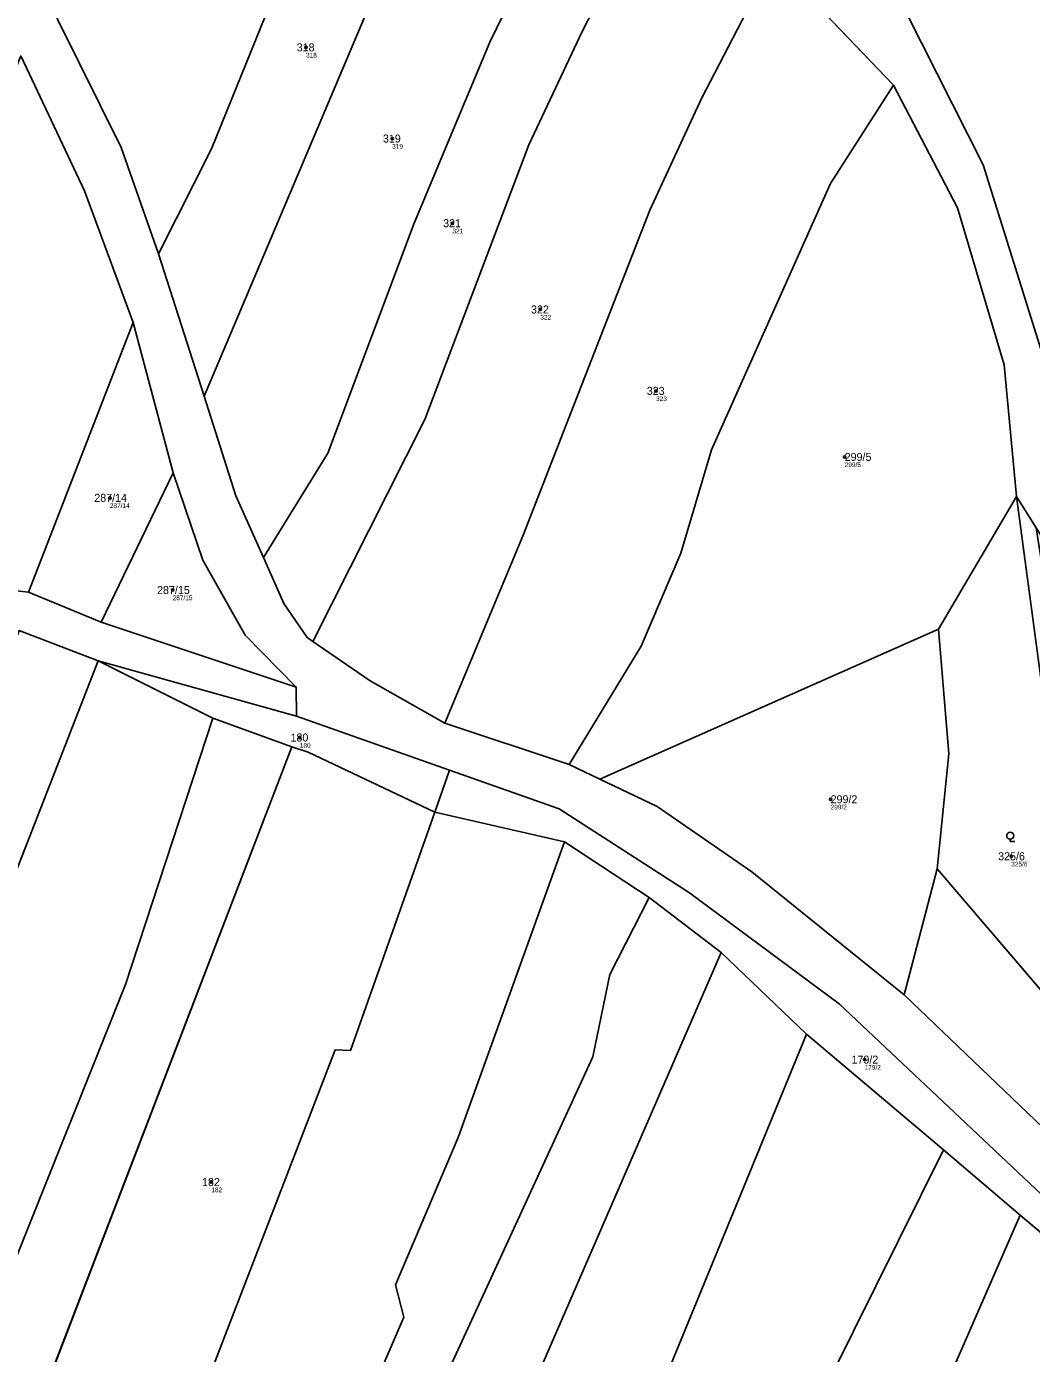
# Model space of a CAD drawing. Extents: x -767985 to -763816, y -1059600 to -1057360.
# Drawn here: x -766182.2 to -765968.6, y -1058497.3 to -1058215.3 of the extents above; entities that cross this region are included whole.
import ezdxf

# ---------------------------------------------------------------- set-up
doc = ezdxf.new("R2010")
doc.units = 0
for name, color, linetype in [('Definiční body', 7, 'Continuous'), ('Hranice parcel', 7, 'Continuous'), ('Parcelní čísla', 7, 'Continuous'), ('Polygon parcely', 7, 'Continuous'), ('Značky kultur', 7, 'Continuous')]:
    doc.layers.add(name, color=color, linetype=linetype)

msp = doc.modelspace()

# ---------------------------------------------------------------- linework, layer by layer
at = {"layer": 'Definiční body'}
for centre in [(-766122.78, -1058219.76994), (-766104.46, -1058239.13994), (-766091.66, -1058257.12994), (-766072.99, -1058275.45994), (-766048.38, -1058292.74994), (-766008.3, -1058306.77994), (-766164.47, -1058315.47994), (-766151.13, -1058335.06994), (-766124.1, -1058366.39994), (-766011.29, -1058379.51994), (-765972.91, -1058391.62994), (-766004.07, -1058434.83994), (-766142.9, -1058460.84994)]:
    msp.add_circle(centre, 0.25, dxfattribs=at)
at = {"layer": 'Hranice parcel'}
for p, q in [((-766144.44, -1058293.9), (-766085.7, -1058155.04)), ((-766023.45, -1058201.07), (-765997.93, -1058227.82)), ((-766144.44, -1058293.9), (-766154.16, -1058263.63)), ((-766181.77, -1058335.55), (-766159.52, -1058278.21)), ((-766159.52, -1058278.21), (-766150.99, -1058310.19)), ((-766166.32, -1058341.89), (-766150.99, -1058310.19)), ((-765988.34, -1058343.38), (-765971.77, -1058315.2)), ((-765967.58, -1058321.82), (-765971.77, -1058315.2)), ((-766181.77, -1058335.55), (-766166.32, -1058341.89)), ((-766166.32, -1058341.89), (-766124.85, -1058355.68)), ((-765988.34, -1058343.38), (-766060.34, -1058375.22)), ((-766166.97, -1058350.08), (-766183.72, -1058343.65)), ((-766166.97, -1058350.08), (-766234.65, -1058523.62)), ((-766124.77, -1058361.86), (-766166.97, -1058350.08)), ((-766166.97, -1058350.08), (-766142.57, -1058362.31)), ((-766124.85, -1058355.68), (-766124.77, -1058361.86)), ((-766125.82, -1058368.4), (-766142.57, -1058362.31)), ((-766124.77, -1058361.86), (-766092.25, -1058373.31)), ((-766066.84, -1058372.11), (-766093.28, -1058363.36)), ((-766193.09, -1058543.53), (-766125.82, -1058368.4)), ((-766092.25, -1058373.31), (-766095.42, -1058382.27)), ((-766060.34, -1058375.22), (-766066.84, -1058372.11)), ((-766067.85, -1058388.57), (-766095.42, -1058382.27)), ((-766049.88, -1058400.36), (-766067.85, -1058388.57)), ((-765995.67, -1058421.04), (-765988.63, -1058394.32)), ((-765936.48, -1058455.29), (-765988.63, -1058394.32)), ((-766034.52, -1058412.06), (-766049.88, -1058400.36)), ((-766016.38, -1058429.41), (-766034.52, -1058412.06)), ((-765987.29, -1058454.03), (-766016.38, -1058429.41)), ((-765970.97, -1058467.85), (-765987.29, -1058454.03)), ((-765949.24, -1058486.24), (-765970.97, -1058467.85))]:
    msp.add_line(p, q, dxfattribs=at)
for points in [[(-766154.16, -1058263.63), (-766142.88, -1058241.36), (-766102.9, -1058142.76)], [(-766131.83, -1058328.16), (-766118.17, -1058305.96), (-766099.79, -1058257.11), (-766083.71, -1058218.7), (-766061.29, -1058172.55)], [(-766121.31, -1058346.01), (-766097.55, -1058298.8), (-766075.41, -1058240.45), (-766064.09, -1058216.4), (-766047.12, -1058183.23)], [(-766093.28, -1058363.36), (-766076.64, -1058323.43), (-766049.74, -1058254.37), (-766038.76, -1058230.6), (-766023.45, -1058201.07)], [(-766154.16, -1058263.63), (-766162.06, -1058241.04), (-766179.98, -1058204.86)], [(-765961.17, -1058301.29), (-765978.87, -1058244.75), (-765995.2, -1058212.34)], [(-766183.4, -1058221.59), (-766169.87, -1058250.23), (-766159.52, -1058278.21)], [(-765997.93, -1058227.82), (-766011.33, -1058248.72), (-766036.6, -1058305.3), (-766043.12, -1058327.25), (-766051.55, -1058347.01), (-766066.84, -1058372.11)], [(-765997.93, -1058227.82), (-765984.33, -1058253.84), (-765974.41, -1058287.25), (-765971.77, -1058315.2)], [(-766131.83, -1058328.16), (-766137.71, -1058315.03), (-766144.44, -1058293.9)], [(-766150.99, -1058310.19), (-766144.69, -1058328.75), (-766135.72, -1058344.67), (-766124.85, -1058355.68)], [(-765971.77, -1058315.2), (-765965.74, -1058360.18), (-765957.89, -1058393.07), (-765936.48, -1058455.29)], [(-766121.31, -1058346.01), (-766122.51, -1058345.18), (-766127.47, -1058337.9), (-766131.83, -1058328.16)], [(-766228.56, -1058334.02), (-766207.88, -1058332.62), (-766181.77, -1058335.55)], [(-765988.63, -1058394.32), (-765986.13, -1058369.89), (-765988.34, -1058343.38)], [(-766093.28, -1058363.36), (-766109.12, -1058354.36), (-766121.31, -1058346.01)], [(-766142.57, -1058362.31), (-766161.12, -1058418.9), (-766208.41, -1058536.69), (-766234.65, -1058523.62)], [(-766125.82, -1058368.4), (-766122.29, -1058369.54), (-766095.42, -1058382.27)], [(-766092.25, -1058373.31), (-766068.95, -1058381.52), (-766041.29, -1058399.4), (-766009.49, -1058422.96), (-765948.22, -1058480.72), (-765893.77, -1058540.14)], [(-766060.34, -1058375.22), (-766048.15, -1058381.06), (-766028.01, -1058394.94), (-765995.67, -1058421.04)], [(-766095.42, -1058382.27), (-766113.31, -1058432.89), (-766116.58, -1058432.79), (-766143.3, -1058502.05), (-766154.19, -1058527.06), (-766168.29, -1058556.08), (-766193.09, -1058543.53)], [(-766169.69, -1058635.49), (-766156.91, -1058609.08), (-766132.92, -1058561.4), (-766102, -1058489.55), (-766103.74, -1058482.68), (-766090.42, -1058451.4), (-766067.85, -1058388.57)], [(-766049.88, -1058400.36), (-766058.24, -1058416.78), (-766061.82, -1058434.27), (-766094.09, -1058504.46), (-766093.62, -1058515.66), (-766151.49, -1058647.82)], [(-766136.72, -1058657.61), (-766084.02, -1058535.83), (-766085.34, -1058529.05), (-766034.52, -1058412.06)], [(-765995.67, -1058421.04), (-765938.28, -1058475.97), (-765907.06, -1058509.99)], [(-766016.38, -1058429.41), (-766050.83, -1058513.25), (-766066.39, -1058553.96), (-766065.8, -1058559.59), (-766086.3, -1058607.64), (-766113.32, -1058673.4)], [(-765987.29, -1058454.03), (-766015.99, -1058511.79), (-766043.07, -1058579.66), (-766045.7, -1058582.49), (-766060.94, -1058615.53), (-766091.43, -1058686.48)], [(-765970.97, -1058467.85), (-765992.67, -1058517.5), (-766028.19, -1058606.49), (-766031.26, -1058616.02), (-766049.02, -1058660.43), (-766066.43, -1058709.63)]]:
    msp.add_lwpolyline(points, dxfattribs=at)
at = {"layer": 'Polygon parcely'}
for points in [[(-766139.56, -1058061.14), (-766134.75, -1058069.91), (-766085.7, -1058155.04), (-766061.29, -1058172.55), (-766047.12, -1058183.23), (-766023.45, -1058201.07), (-765997.93, -1058227.82), (-765984.33, -1058253.84), (-765974.41, -1058287.25), (-765971.77, -1058315.2), (-765967.58, -1058321.82), (-765926.48, -1058386.74), (-765928.93, -1058373.47), (-765954.8, -1058330.58), (-765965, -1058312.91), (-765961.17, -1058301.29), (-765978.87, -1058244.75), (-765995.2, -1058212.34), (-766007.59, -1058201.19), (-766083.69, -1058146.62), (-766127.9, -1058069.32)], [(-765907.06, -1058509.99), (-765938.28, -1058475.97), (-765995.67, -1058421.04), (-766028.01, -1058394.94), (-766048.15, -1058381.06), (-766060.34, -1058375.22), (-766066.84, -1058372.11), (-766093.28, -1058363.36), (-766109.12, -1058354.36), (-766121.31, -1058346.01), (-766122.51, -1058345.18), (-766127.47, -1058337.9), (-766131.83, -1058328.16), (-766137.71, -1058315.03), (-766144.44, -1058293.9), (-766154.16, -1058263.63), (-766162.06, -1058241.04), (-766179.98, -1058204.86), (-766190.76, -1058186.25)], [(-766183.4, -1058221.59), (-766169.87, -1058250.23), (-766159.52, -1058278.21), (-766150.99, -1058310.19), (-766144.69, -1058328.75), (-766135.72, -1058344.67), (-766124.85, -1058355.68), (-766124.77, -1058361.86), (-766092.25, -1058373.31), (-766068.95, -1058381.52), (-766041.29, -1058399.4), (-766009.49, -1058422.96), (-765948.22, -1058480.72), (-765893.77, -1058540.14)], [(-766183.72, -1058343.65), (-766166.97, -1058350.08), (-766124.77, -1058361.86), (-766124.85, -1058355.68), (-766166.32, -1058341.89), (-766181.77, -1058335.55), (-766207.88, -1058332.62)]]:
    msp.add_lwpolyline(points, dxfattribs=at)
for points in [[(-765951.27, -1058110.93), (-765967.67, -1058152.53), (-765995.2, -1058212.34), (-765978.87, -1058244.75), (-765961.17, -1058301.29), (-765953.25, -1058277.24), (-765935.05, -1058241.06), (-765926.19, -1058210.84), (-765915.4, -1058188.6), (-765899.83, -1058140.73), (-765881.35, -1058082.33), (-765876.43, -1058058.91), (-765944.68, -1058083.49)], [(-766154.16, -1058263.63), (-766142.88, -1058241.36), (-766102.9, -1058142.76), (-766140.77, -1058122.43), (-766167.14, -1058177.82), (-766179.98, -1058204.86), (-766162.06, -1058241.04)], [(-766144.44, -1058293.9), (-766085.7, -1058155.04), (-766102.9, -1058142.76), (-766142.88, -1058241.36), (-766154.16, -1058263.63)], [(-766099.79, -1058257.11), (-766083.71, -1058218.7), (-766061.29, -1058172.55), (-766085.7, -1058155.04), (-766144.44, -1058293.9), (-766137.71, -1058315.03), (-766131.83, -1058328.16), (-766118.17, -1058305.96)], [(-766075.41, -1058240.45), (-766064.09, -1058216.4), (-766047.12, -1058183.23), (-766061.29, -1058172.55), (-766083.71, -1058218.7), (-766099.79, -1058257.11), (-766118.17, -1058305.96), (-766131.83, -1058328.16), (-766127.47, -1058337.9), (-766122.51, -1058345.18), (-766121.31, -1058346.01), (-766097.55, -1058298.8)], [(-766038.76, -1058230.6), (-766023.45, -1058201.07), (-766047.12, -1058183.23), (-766064.09, -1058216.4), (-766075.41, -1058240.45), (-766097.55, -1058298.8), (-766121.31, -1058346.01), (-766109.12, -1058354.36), (-766093.28, -1058363.36), (-766076.64, -1058323.43), (-766049.74, -1058254.37)], [(-766093.28, -1058363.36), (-766066.84, -1058372.11), (-766051.55, -1058347.01), (-766043.12, -1058327.25), (-766036.6, -1058305.3), (-766011.33, -1058248.72), (-765997.93, -1058227.82), (-766023.45, -1058201.07), (-766038.76, -1058230.6), (-766049.74, -1058254.37), (-766076.64, -1058323.43)], [(-766207.88, -1058332.62), (-766181.77, -1058335.55), (-766159.52, -1058278.21), (-766169.87, -1058250.23), (-766183.4, -1058221.59), (-766228.56, -1058334.02)], [(-766011.33, -1058248.72), (-766036.6, -1058305.3), (-766043.12, -1058327.25), (-766051.55, -1058347.01), (-766066.84, -1058372.11), (-766060.34, -1058375.22), (-765988.34, -1058343.38), (-765971.77, -1058315.2), (-765974.41, -1058287.25), (-765984.33, -1058253.84), (-765997.93, -1058227.82)], [(-766166.32, -1058341.89), (-766150.99, -1058310.19), (-766159.52, -1058278.21), (-766181.77, -1058335.55)], [(-766166.32, -1058341.89), (-766124.85, -1058355.68), (-766135.72, -1058344.67), (-766144.69, -1058328.75), (-766150.99, -1058310.19)], [(-765988.34, -1058343.38), (-765986.13, -1058369.89), (-765988.63, -1058394.32), (-765936.48, -1058455.29), (-765957.89, -1058393.07), (-765965.74, -1058360.18), (-765971.77, -1058315.2)], [(-765907.06, -1058509.99), (-765911.75, -1058480.2), (-765934.26, -1058454.57), (-765954.3, -1058391.92), (-765961.05, -1058364.02), (-765967.58, -1058321.82), (-765971.77, -1058315.2), (-765965.74, -1058360.18), (-765957.89, -1058393.07), (-765936.48, -1058455.29), (-765915.57, -1058480.19)], [(-766028.01, -1058394.94), (-765995.67, -1058421.04), (-765988.63, -1058394.32), (-765986.13, -1058369.89), (-765988.34, -1058343.38), (-766060.34, -1058375.22), (-766048.15, -1058381.06)], [(-766264.31, -1058548.78), (-766250.27, -1058554.82), (-766234.65, -1058523.62), (-766166.97, -1058350.08), (-766183.72, -1058343.65), (-766211.11, -1058416.66)], [(-766234.65, -1058523.62), (-766208.41, -1058536.69), (-766161.12, -1058418.9), (-766142.57, -1058362.31), (-766166.97, -1058350.08)], [(-766166.97, -1058350.08), (-766142.57, -1058362.31), (-766125.82, -1058368.4), (-766122.29, -1058369.54), (-766095.42, -1058382.27), (-766092.25, -1058373.31), (-766124.77, -1058361.86)], [(-766193.09, -1058543.53), (-766125.82, -1058368.4), (-766142.57, -1058362.31), (-766161.12, -1058418.9), (-766208.41, -1058536.69), (-766234.65, -1058523.62), (-766250.27, -1058554.82), (-766255.7, -1058573.98), (-766240.75, -1058584.79), (-766221.41, -1058602.76)], [(-766193.09, -1058543.53), (-766168.29, -1058556.08), (-766154.19, -1058527.06), (-766143.3, -1058502.05), (-766116.58, -1058432.79), (-766113.31, -1058432.89), (-766095.42, -1058382.27), (-766122.29, -1058369.54), (-766125.82, -1058368.4)], [(-766095.42, -1058382.27), (-766067.85, -1058388.57), (-766049.88, -1058400.36), (-766034.52, -1058412.06), (-766016.38, -1058429.41), (-765987.29, -1058454.03), (-765970.97, -1058467.85), (-765949.24, -1058486.24), (-765939.32, -1058499.61), (-765915.25, -1058521.03), (-765893.77, -1058540.14), (-765948.22, -1058480.72), (-766009.49, -1058422.96), (-766041.29, -1058399.4), (-766068.95, -1058381.52), (-766092.25, -1058373.31)], [(-766103.74, -1058482.68), (-766090.42, -1058451.4), (-766067.85, -1058388.57), (-766095.42, -1058382.27), (-766113.31, -1058432.89), (-766116.58, -1058432.79), (-766143.3, -1058502.05), (-766154.19, -1058527.06), (-766168.29, -1058556.08), (-766193.09, -1058543.53), (-766221.41, -1058602.76), (-766208.62, -1058614.63), (-766179.38, -1058630.04), (-766169.69, -1058635.49), (-766156.91, -1058609.08), (-766132.92, -1058561.4), (-766102, -1058489.55)], [(-766067.85, -1058388.57), (-766090.42, -1058451.4), (-766103.74, -1058482.68), (-766102, -1058489.55), (-766132.92, -1058561.4), (-766156.91, -1058609.08), (-766169.69, -1058635.49), (-766151.49, -1058647.82), (-766093.62, -1058515.66), (-766094.09, -1058504.46), (-766061.82, -1058434.27), (-766058.24, -1058416.78), (-766049.88, -1058400.36)], [(-765938.28, -1058475.97), (-765907.06, -1058509.99), (-765915.57, -1058480.19), (-765936.48, -1058455.29), (-765988.63, -1058394.32), (-765995.67, -1058421.04)], [(-766093.62, -1058515.66), (-766151.49, -1058647.82), (-766136.72, -1058657.61), (-766084.02, -1058535.83), (-766085.34, -1058529.05), (-766034.52, -1058412.06), (-766049.88, -1058400.36), (-766058.24, -1058416.78), (-766061.82, -1058434.27), (-766094.09, -1058504.46)], [(-766034.52, -1058412.06), (-766085.34, -1058529.05), (-766084.02, -1058535.83), (-766136.72, -1058657.61), (-766113.32, -1058673.4), (-766086.3, -1058607.64), (-766065.8, -1058559.59), (-766066.39, -1058553.96), (-766050.83, -1058513.25), (-766016.38, -1058429.41)], [(-766066.39, -1058553.96), (-766065.8, -1058559.59), (-766086.3, -1058607.64), (-766113.32, -1058673.4), (-766091.43, -1058686.48), (-766060.94, -1058615.53), (-766045.7, -1058582.49), (-766043.07, -1058579.66), (-766015.99, -1058511.79), (-765987.29, -1058454.03), (-766016.38, -1058429.41), (-766050.83, -1058513.25)], [(-766091.43, -1058686.48), (-766066.43, -1058709.63), (-766049.02, -1058660.43), (-766031.26, -1058616.02), (-766028.19, -1058606.49), (-765992.67, -1058517.5), (-765970.97, -1058467.85), (-765987.29, -1058454.03), (-766015.99, -1058511.79), (-766043.07, -1058579.66), (-766045.7, -1058582.49), (-766060.94, -1058615.53)], [(-765970.97, -1058467.85), (-765992.67, -1058517.5), (-766028.19, -1058606.49), (-766031.26, -1058616.02), (-766049.02, -1058660.43), (-766066.43, -1058709.63), (-766042.69, -1058716.31), (-766022.63, -1058667.68), (-765975.64, -1058550.3), (-765967.46, -1058526.34), (-765949.24, -1058486.24)]]:
    msp.add_lwpolyline(points, close=True, dxfattribs=at)
at = {"layer": 'Značky kultur'}
for p, q in [((-765973.12, -1058388.022), (-765973.12, -1058388.52)), ((-765973.12, -1058388.52), (-765972.119, -1058388.52))]:
    msp.add_line(p, q, dxfattribs=at)
msp.add_circle((-765973.11929, -1058387.2709), 0.75, dxfattribs=at)

# ---------------------------------------------------------------- texts
at = {"layer": 'Definiční body'}
for s, p in [('318', (-766122.78, -1058221.926)), ('319', (-766104.46, -1058241.296)), ('321', (-766091.66, -1058259.286)), ('322', (-766072.99, -1058277.616)), ('323', (-766048.38, -1058294.906)), ('299/5', (-766008.3, -1058308.936)), ('287/14', (-766164.47, -1058317.636)), ('287/15', (-766151.13, -1058337.226)), ('180', (-766124.1, -1058368.556)), ('299/2', (-766011.29, -1058381.676)), ('325/6', (-765972.91, -1058393.786)), ('179/2', (-766004.07, -1058436.996)), ('182', (-766142.9, -1058463.006))]:
    msp.add_text(s, height=0.999996, dxfattribs=at).set_placement(p)
at = {"layer": 'Parcelní čísla'}
for s, p in [('318', (-766124.754, -1058220.62)), ('319', (-766106.434, -1058239.99)), ('321', (-766093.634, -1058257.98)), ('322', (-766074.964, -1058276.31)), ('323', (-766050.354, -1058293.6)), ('299/5', (-766008.3, -1058307.63)), ('287/14', (-766167.775, -1058316.33)), ('287/15', (-766154.435, -1058335.92)), ('180', (-766126.074, -1058367.25)), ('299/2', (-766011.29, -1058380.37)), ('325/6', (-765975.683, -1058392.48)), ('179/2', (-766006.843, -1058435.69)), ('182', (-766144.874, -1058461.7))]:
    msp.add_text(s, height=1.699998, dxfattribs=at).set_placement(p)

doc.saveas('drawing.dxf')
